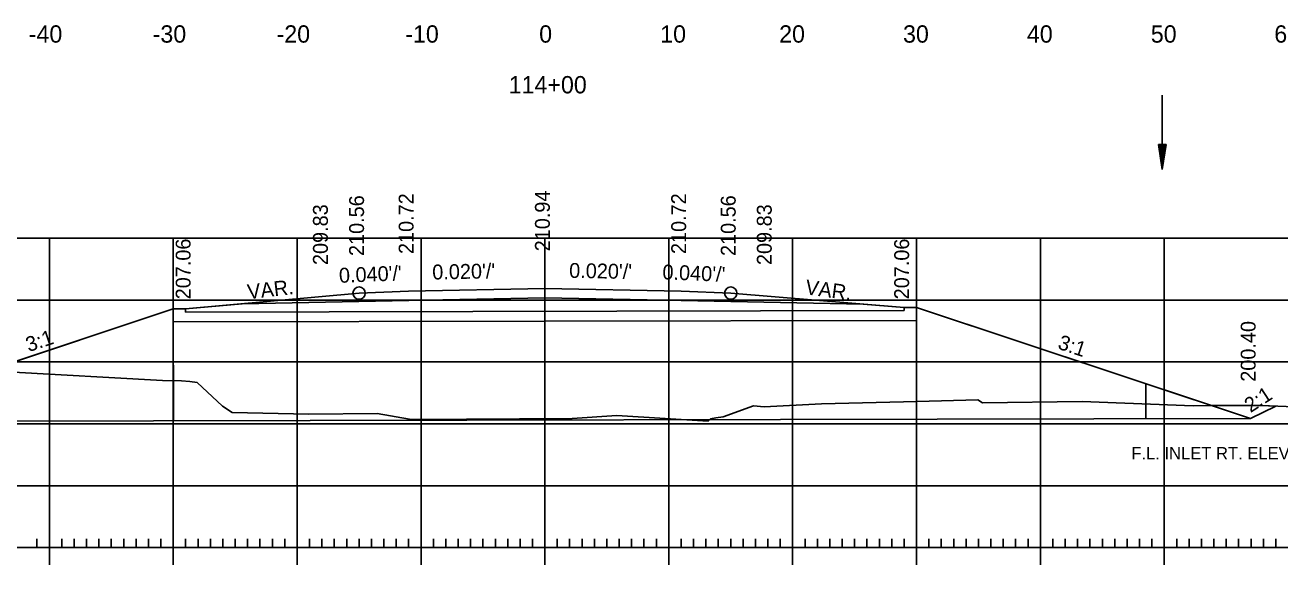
# Model space of a CAD drawing. Extents: x 1312042 to 1371461, y 379929 to 1834241.
# Drawn here: x 1371256.3 to 1371357.6, y 380032.5 to 380076.1 of the extents above; entities that cross this region are included whole.
import ezdxf

# ---------------------------------------------------------------- set-up
doc = ezdxf.new("R2010")
doc.units = 0
for name, color, linetype in [('R_Alt Surface', 7, 'Continuous'), ('R_Axis', 7, 'Continuous'), ('R_Axis Annot', 7, 'Continuous'), ('R_Exist Surface', 7, 'Continuous'), ('R_Fin Surface', 7, 'Continuous'), ('R_Grid', 7, 'Continuous'), ('R_No Plot', 7, 'Continuous'), ('R_Water', 7, 'Continuous'), ('R_Water Annot', 7, 'Continuous'), ('R_Xsect Elev', 7, 'Continuous'), ('R_Xsect Slope', 7, 'Continuous')]:
    doc.layers.add(name, color=color, linetype=linetype)

msp = doc.modelspace()

# ---------------------------------------------------------------- linework, layer by layer
at = {"layer": 'R_Alt Surface'}
msp.add_lwpolyline([(1371273.84, 380053.61), (1371287.29, 380053.88), (1371298.28, 380054.1), (1371309.29, 380053.88), (1371323.97, 380053.58)], dxfattribs=at)
at = {"layer": 'R_Axis'}
for p, q in [((1371258.28, 380032.51), (1371258.28, 380035.31)), ((1371268.28, 380032.51), (1371268.28, 380035.31)), ((1371278.28, 380032.51), (1371278.28, 380035.31)), ((1371288.28, 380032.51), (1371288.28, 380035.31)), ((1371298.28, 380032.51), (1371298.28, 380035.31)), ((1371308.28, 380032.51), (1371308.28, 380035.31)), ((1371318.28, 380032.51), (1371318.28, 380035.31)), ((1371328.28, 380032.51), (1371328.28, 380035.31)), ((1371338.28, 380032.51), (1371338.28, 380035.31)), ((1371348.28, 380032.51), (1371348.28, 380035.31)), ((1371257.28, 380033.91), (1371257.28, 380034.61)), ((1371259.28, 380033.91), (1371259.28, 380034.61)), ((1371260.28, 380033.91), (1371260.28, 380034.61)), ((1371261.28, 380033.91), (1371261.28, 380034.61)), ((1371262.28, 380033.91), (1371262.28, 380034.61)), ((1371263.28, 380033.91), (1371263.28, 380034.61)), ((1371264.28, 380033.91), (1371264.28, 380034.61)), ((1371265.28, 380033.91), (1371265.28, 380034.61)), ((1371266.28, 380033.91), (1371266.28, 380034.61)), ((1371267.28, 380033.91), (1371267.28, 380034.61)), ((1371269.28, 380033.91), (1371269.28, 380034.61)), ((1371270.28, 380033.91), (1371270.28, 380034.61)), ((1371271.28, 380033.91), (1371271.28, 380034.61)), ((1371272.28, 380033.91), (1371272.28, 380034.61)), ((1371273.28, 380033.91), (1371273.28, 380034.61)), ((1371274.28, 380033.91), (1371274.28, 380034.61)), ((1371275.28, 380033.91), (1371275.28, 380034.61)), ((1371276.28, 380033.91), (1371276.28, 380034.61)), ((1371277.28, 380033.91), (1371277.28, 380034.61)), ((1371279.28, 380033.91), (1371279.28, 380034.61)), ((1371280.28, 380033.91), (1371280.28, 380034.61)), ((1371281.28, 380033.91), (1371281.28, 380034.61)), ((1371282.28, 380033.91), (1371282.28, 380034.61)), ((1371283.28, 380033.91), (1371283.28, 380034.61)), ((1371284.28, 380033.91), (1371284.28, 380034.61)), ((1371285.28, 380033.91), (1371285.28, 380034.61)), ((1371286.28, 380033.91), (1371286.28, 380034.61)), ((1371287.28, 380033.91), (1371287.28, 380034.61)), ((1371289.28, 380033.91), (1371289.28, 380034.61)), ((1371290.28, 380033.91), (1371290.28, 380034.61)), ((1371291.28, 380033.91), (1371291.28, 380034.61)), ((1371292.28, 380033.91), (1371292.28, 380034.61)), ((1371293.28, 380033.91), (1371293.28, 380034.61)), ((1371294.28, 380033.91), (1371294.28, 380034.61)), ((1371295.28, 380033.91), (1371295.28, 380034.61)), ((1371296.28, 380033.91), (1371296.28, 380034.61)), ((1371297.28, 380033.91), (1371297.28, 380034.61)), ((1371299.28, 380033.91), (1371299.28, 380034.61)), ((1371300.28, 380033.91), (1371300.28, 380034.61)), ((1371301.28, 380033.91), (1371301.28, 380034.61)), ((1371302.28, 380033.91), (1371302.28, 380034.61)), ((1371303.28, 380033.91), (1371303.28, 380034.61)), ((1371304.28, 380033.91), (1371304.28, 380034.61)), ((1371305.28, 380033.91), (1371305.28, 380034.61)), ((1371306.28, 380033.91), (1371306.28, 380034.61)), ((1371307.28, 380033.91), (1371307.28, 380034.61)), ((1371309.28, 380033.91), (1371309.28, 380034.61)), ((1371310.28, 380033.91), (1371310.28, 380034.61)), ((1371311.28, 380033.91), (1371311.28, 380034.61)), ((1371312.28, 380033.91), (1371312.28, 380034.61)), ((1371313.28, 380033.91), (1371313.28, 380034.61)), ((1371314.28, 380033.91), (1371314.28, 380034.61)), ((1371315.28, 380033.91), (1371315.28, 380034.61)), ((1371316.28, 380033.91), (1371316.28, 380034.61)), ((1371317.28, 380033.91), (1371317.28, 380034.61)), ((1371319.28, 380033.91), (1371319.28, 380034.61)), ((1371320.28, 380033.91), (1371320.28, 380034.61)), ((1371321.28, 380033.91), (1371321.28, 380034.61)), ((1371322.28, 380033.91), (1371322.28, 380034.61)), ((1371323.28, 380033.91), (1371323.28, 380034.61)), ((1371324.28, 380033.91), (1371324.28, 380034.61)), ((1371325.28, 380033.91), (1371325.28, 380034.61)), ((1371326.28, 380033.91), (1371326.28, 380034.61)), ((1371327.28, 380033.91), (1371327.28, 380034.61)), ((1371329.28, 380033.91), (1371329.28, 380034.61)), ((1371330.28, 380033.91), (1371330.28, 380034.61)), ((1371331.28, 380033.91), (1371331.28, 380034.61)), ((1371332.28, 380033.91), (1371332.28, 380034.61)), ((1371333.28, 380033.91), (1371333.28, 380034.61)), ((1371334.28, 380033.91), (1371334.28, 380034.61)), ((1371335.28, 380033.91), (1371335.28, 380034.61)), ((1371336.28, 380033.91), (1371336.28, 380034.61)), ((1371337.28, 380033.91), (1371337.28, 380034.61)), ((1371339.28, 380033.91), (1371339.28, 380034.61)), ((1371340.28, 380033.91), (1371340.28, 380034.61)), ((1371341.28, 380033.91), (1371341.28, 380034.61)), ((1371342.28, 380033.91), (1371342.28, 380034.61)), ((1371343.28, 380033.91), (1371343.28, 380034.61)), ((1371344.28, 380033.91), (1371344.28, 380034.61)), ((1371345.28, 380033.91), (1371345.28, 380034.61)), ((1371346.28, 380033.91), (1371346.28, 380034.61)), ((1371347.28, 380033.91), (1371347.28, 380034.61)), ((1371349.28, 380033.91), (1371349.28, 380034.61)), ((1371350.28, 380033.91), (1371350.28, 380034.61)), ((1371351.28, 380033.91), (1371351.28, 380034.61)), ((1371352.28, 380033.91), (1371352.28, 380034.61)), ((1371353.28, 380033.91), (1371353.28, 380034.61)), ((1371354.28, 380033.91), (1371354.28, 380034.61)), ((1371355.28, 380033.91), (1371355.28, 380034.61)), ((1371356.28, 380033.91), (1371356.28, 380034.61)), ((1371357.28, 380033.91), (1371357.28, 380034.61)), ((1371158.28, 380033.91), (1371438.28, 380033.91))]:
    msp.add_line(p, q, dxfattribs=at)
at = {"layer": 'R_Exist Surface'}
msp.add_lwpolyline([(1371254.91, 380048.1), (1371267.41, 380047.41), (1371268.96, 380047.38), (1371269.62, 380047.34), (1371270.2, 380047.25), (1371272.25, 380045.33), (1371273.03, 380044.82), (1371279.23, 380044.69), (1371284.73, 380044.75), (1371287.35, 380044.29), (1371287.7, 380044.25), (1371300.48, 380044.34), (1371304.09, 380044.57), (1371311.45, 380044.13), (1371311.66, 380044.31), (1371312.08, 380044.39), (1371312.66, 380044.47), (1371315.11, 380045.36), (1371315.98, 380045.28), (1371320.6, 380045.53), (1371328.32, 380045.72), (1371333.22, 380045.85), (1371333.6, 380045.61), (1371341.66, 380045.71), (1371350.61, 380045.37), (1371356.11, 380045.39), (1371374.89, 380044.65)], dxfattribs=at)
at = {"layer": 'R_Fin Surface'}
msp.add_lwpolyline([(1371232.95, 380046.77), (1371240.98, 380044.09), (1371268.27, 380053.19), (1371269.27, 380053.19), (1371283.28, 380054.47), (1371287.28, 380054.63), (1371298.28, 380054.85), (1371309.28, 380054.63), (1371313.28, 380054.47), (1371327.27, 380053.31), (1371328.27, 380053.31), (1371355.24, 380044.33), (1371357.28, 380045.35)], dxfattribs=at)
at = {"layer": 'R_Grid'}
for p, q in [((1371158.28, 380058.91), (1371438.28, 380058.91)), ((1371258.28, 380033.91), (1371258.28, 380058.91)), ((1371268.28, 380033.91), (1371268.28, 380058.91)), ((1371278.28, 380033.91), (1371278.28, 380058.91)), ((1371288.28, 380033.91), (1371288.28, 380058.91)), ((1371298.28, 380033.91), (1371298.28, 380058.91)), ((1371308.28, 380033.91), (1371308.28, 380058.91)), ((1371318.28, 380033.91), (1371318.28, 380058.91)), ((1371328.28, 380033.91), (1371328.28, 380058.91)), ((1371338.28, 380033.91), (1371338.28, 380058.91)), ((1371348.28, 380033.91), (1371348.28, 380058.91)), ((1371158.28, 380053.91), (1371438.28, 380053.91)), ((1371158.28, 380048.91), (1371438.28, 380048.91)), ((1371158.28, 380043.91), (1371438.28, 380043.91)), ((1371158.28, 380038.91), (1371438.28, 380038.91)), ((1371158.28, 380033.91), (1371438.28, 380033.91))]:
    msp.add_line(p, q, dxfattribs=at)
at = {"layer": 'R_No Plot'}
msp.add_lwpolyline([(1371254.91, 380048.1), (1371267.41, 380047.41), (1371268.96, 380047.38), (1371269.62, 380047.34), (1371270.2, 380047.25), (1371272.25, 380045.33), (1371273.03, 380044.82), (1371279.23, 380044.69), (1371284.73, 380044.75), (1371287.35, 380044.29), (1371287.7, 380044.25), (1371300.48, 380044.34), (1371304.09, 380044.57), (1371311.45, 380044.13), (1371311.66, 380044.31), (1371312.08, 380044.39), (1371312.66, 380044.47), (1371315.11, 380045.36), (1371315.98, 380045.28), (1371320.6, 380045.53), (1371328.32, 380045.72), (1371333.22, 380045.85), (1371333.6, 380045.61), (1371341.66, 380045.71), (1371350.61, 380045.37), (1371352.08, 380045.38), (1371328.27, 380053.31), (1371327.27, 380053.31), (1371323.97, 380053.58), (1371309.29, 380053.88), (1371298.28, 380054.1), (1371287.29, 380053.88), (1371273.84, 380053.61), (1371269.27, 380053.19), (1371268.27, 380053.19), (1371253.25, 380048.18)], dxfattribs=at)
msp.add_lwpolyline([(1371352.08, 380045.38), (1371356.11, 380045.39), (1371357.28, 380045.35), (1371355.24, 380044.33)], close=True, dxfattribs=at)
for centre in [(1371283.28, 380054.47), (1371313.28, 380054.47)]:
    msp.add_circle(centre, 0.5, dxfattribs=at)
at = {"layer": 'R_Water'}
for p, q in [((1371268.27, 380053.19), (1371268.29, 380044.15)), ((1371269.27, 380053.19), (1371269.27, 380052.94)), ((1371327.27, 380053.06), (1371269.27, 380052.94)), ((1371327.27, 380053.31), (1371327.27, 380053.06)), ((1371328.27, 380053.31), (1371328.29, 380044.27)), ((1371328.28, 380052.27), (1371268.28, 380052.15)), ((1371346.79, 380047.14), (1371346.79, 380044.31)), ((1371355.24, 380044.33), (1371240.98, 380044.09))]:
    msp.add_line(p, q, dxfattribs=at)
at = {"layer": 'R_Water Annot'}
for p, q in [((1371348.12, 380070.47), (1371348.12, 380064.47)), ((1371347.82, 380066.47), (1371348.12, 380064.47)), ((1371348.42, 380066.47), (1371347.82, 380066.47)), ((1371347.87, 380066.47), (1371348.12, 380064.81)), ((1371347.92, 380066.47), (1371348.12, 380065.15)), ((1371347.97, 380066.47), (1371348.12, 380065.48)), ((1371348.02, 380066.47), (1371348.12, 380065.82)), ((1371348.07, 380066.47), (1371348.12, 380066.16)), ((1371348.42, 380066.47), (1371348.12, 380064.47)), ((1371348.21, 380066.47), (1371348.12, 380065.82)), ((1371348.31, 380066.47), (1371348.12, 380065.15)), ((1371348.37, 380066.47), (1371348.12, 380064.81)), ((1371348.26, 380066.47), (1371348.12, 380065.48)), ((1371348.16, 380066.47), (1371348.12, 380066.16))]:
    msp.add_line(p, q, dxfattribs=at)

# ---------------------------------------------------------------- texts
at = {"layer": 'R_Axis Annot'}
for s, height, p in [('-40', 1.4, (1371256.62, 380074.71)), ('-30', 1.4, (1371266.62, 380074.71)), ('-20', 1.4, (1371276.62, 380074.71)), ('-10', 1.4, (1371287.01, 380074.71)), ('0', 1.4, (1371297.82, 380074.71)), ('10', 1.4, (1371307.59, 380074.71)), ('20', 1.4, (1371317.19, 380074.71)), ('30', 1.4, (1371327.19, 380074.71)), ('40', 1.4, (1371337.19, 380074.71)), ('50', 1.4, (1371347.19, 380074.71)), ('60', 1.4, (1371357.16, 380074.71)), ('114+00', 1.4, (1371295.36, 380070.61)), ('F.L. INLET RT. ELEV. = 200.40', 1, (1371345.62, 380041.03))]:
    msp.add_text(s, height=height, dxfattribs=at).set_placement(p)
at = {"layer": 'R_Xsect Elev'}
for s, p in [('210.94', (1371298.68, 380057.85)), ('209.83', (1371280.76, 380056.74)), ('210.56', (1371283.68, 380057.47)), ('210.72', (1371287.68, 380057.63)), ('210.72', (1371309.68, 380057.63)), ('210.56', (1371313.68, 380057.47)), ('209.83', (1371316.59, 380056.74)), ('207.06', (1371269.68, 380053.97)), ('207.06', (1371327.68, 380053.97)), ('200.40', (1371355.65, 380047.31))]:
    msp.add_text(s, height=1.2, rotation=90, dxfattribs=at).set_placement(p)
at = {"layer": 'R_Xsect Slope'}
for s, rotation, p in [("0.040'/'", 2.2906, (1371281.68, 380055.3)), ("0.020'/'", 1.1458, (1371289.2, 380055.57)), ("0.020'/'", 358.8542, (1371300.23, 380055.71)), ("0.040'/'", 357.7094, (1371307.75, 380055.59)), ('VAR.', 6.55, (1371274.33, 380053.97)), ('VAR.', 352.3529, (1371319.25, 380054.38)), ('3:1', 18.4349, (1371256.61, 380049.7)), ('3:1', 341.5651, (1371339.61, 380050)), ('2:1', 33.0239, (1371355.24, 380044.77))]:
    msp.add_text(s, height=1.2, rotation=rotation, dxfattribs=at).set_placement(p)

doc.saveas('drawing.dxf')
